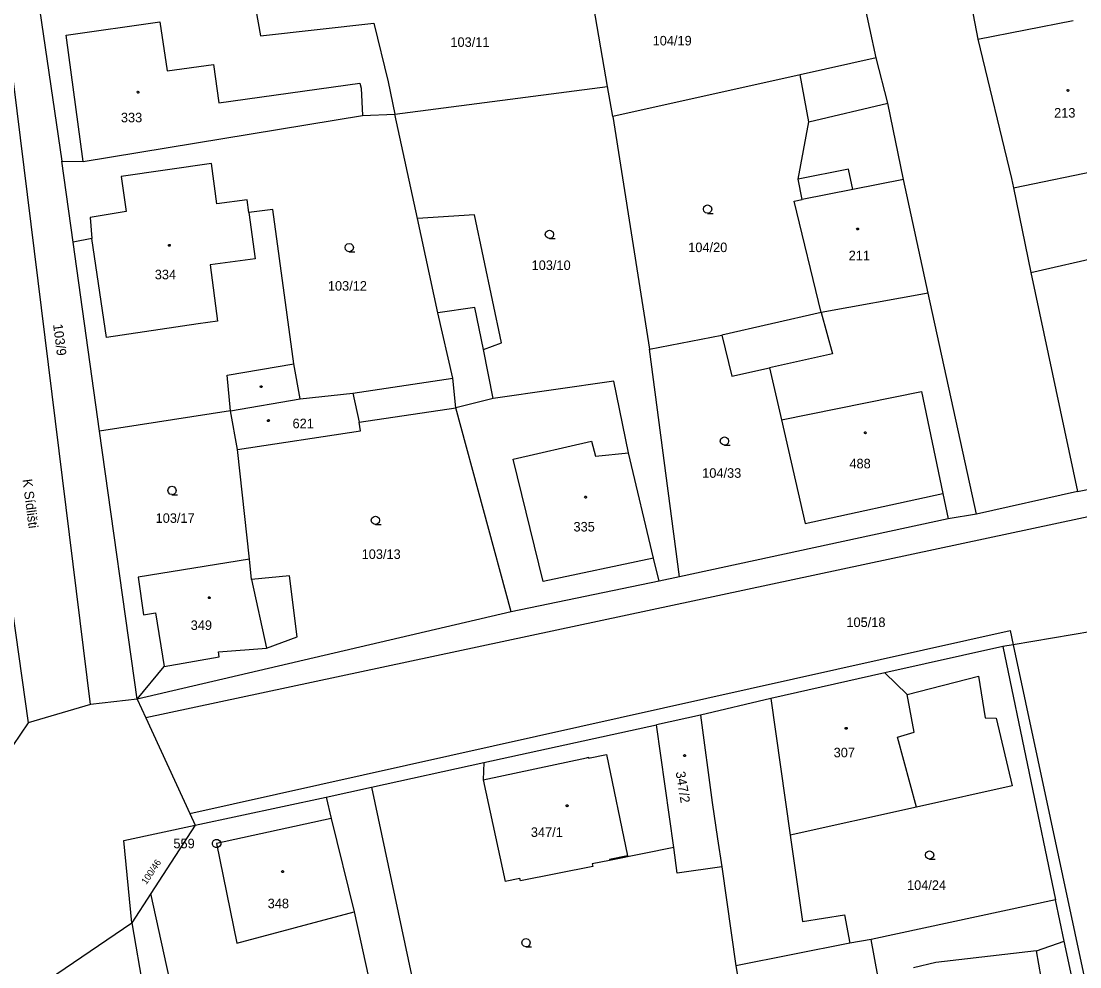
# Model space of a CAD drawing. Extents: x -757994 to -755874, y -1047691 to -1046119.
# Drawn here: x -756803.8 to -756709.6, y -1047154.8 to -1047070.7 of the extents above; entities that cross this region are included whole.
import ezdxf

# ---------------------------------------------------------------- set-up
doc = ezdxf.new("R2010")
doc.units = 0
doc.layers.add('katastrální mapa', color=7, linetype='Continuous')

msp = doc.modelspace()

# ---------------------------------------------------------------- linework, layer by layer
at = {"layer": 'katastrální mapa'}
for p, q in [((-756797.61, -1047131.45), (-756806.3, -1047061.1)), ((-756720.43, -1047063.09), (-756718.67, -1047072.24)), ((-756751.62, -1047076.46), (-756753.8, -1047063.79)), ((-756802.33, -1047068.26), (-756800.17, -1047083.12)), ((-756727.73, -1047073.91), (-756728.84, -1047068.66)), ((-756782.9, -1047069.63), (-756782.48, -1047071.96)), ((-756799.78, -1047071.9), (-756791.44, -1047070.7)), ((-756791.44, -1047070.7), (-756790.78, -1047075.08)), ((-756782.48, -1047071.96), (-756772.4, -1047070.84)), ((-756772.4, -1047070.84), (-756771.14, -1047076.04)), ((-756718.67, -1047072.24), (-756710.2, -1047070.6)), ((-756798.25, -1047083.13), (-756799.78, -1047071.9)), ((-756718.67, -1047072.24), (-756715.68, -1047084.65)), ((-756790.78, -1047075.08), (-756786.68, -1047074.51)), ((-756786.68, -1047074.51), (-756786.2, -1047077.93)), ((-756727.73, -1047073.91), (-756734.49, -1047075.42)), ((-756726.68, -1047077.94), (-756727.73, -1047073.91)), ((-756734.49, -1047075.42), (-756751.14, -1047079.14)), ((-756733.7, -1047079.62), (-756734.49, -1047075.42)), ((-756786.2, -1047077.93), (-756773.64, -1047076.18)), ((-756773.64, -1047076.18), (-756773.52, -1047076.61)), ((-756771.14, -1047076.04), (-756770.54, -1047078.93)), ((-756770.54, -1047078.93), (-756751.62, -1047076.46)), ((-756751.14, -1047079.14), (-756751.62, -1047076.46)), ((-756773.52, -1047076.61), (-756773.43, -1047079.05)), ((-756733.7, -1047079.62), (-756726.68, -1047077.94)), ((-756725.3, -1047084.75), (-756726.68, -1047077.94)), ((-756798.25, -1047083.13), (-756773.43, -1047079.05)), ((-756773.43, -1047079.05), (-756770.54, -1047078.93)), ((-756768.53, -1047088.21), (-756770.54, -1047078.93)), ((-756751.14, -1047079.14), (-756747.9, -1047099.85)), ((-756734.67, -1047084.72), (-756733.7, -1047079.62)), ((-756799.16, -1047090.3), (-756800.17, -1047083.12)), ((-756800.17, -1047083.12), (-756798.25, -1047083.13)), ((-756715.51, -1047085.47), (-756703.12, -1047082.93)), ((-756786.86, -1047083.32), (-756794.88, -1047084.47)), ((-756786.37, -1047086.91), (-756786.86, -1047083.32)), ((-756730.17, -1047083.83), (-756734.67, -1047084.72)), ((-756729.81, -1047085.64), (-756730.17, -1047083.83)), ((-756794.88, -1047084.47), (-756794.45, -1047087.6)), ((-756734.31, -1047086.53), (-756734.67, -1047084.72)), ((-756725.3, -1047084.75), (-756729.81, -1047085.64)), ((-756723.09, -1047094.85), (-756725.3, -1047084.75)), ((-756715.68, -1047084.65), (-756715.51, -1047085.47)), ((-756729.81, -1047085.64), (-756734.31, -1047086.53)), ((-756715.51, -1047085.47), (-756713.97, -1047093.01)), ((-756783.68, -1047086.54), (-756786.37, -1047086.91)), ((-756783.52, -1047087.68), (-756783.68, -1047086.54)), ((-756735.01, -1047086.67), (-756734.31, -1047086.53)), ((-756732.6, -1047096.58), (-756735.01, -1047086.67)), ((-756794.45, -1047087.6), (-756797.65, -1047088.11)), ((-756781.38, -1047087.4), (-756783.52, -1047087.68)), ((-756783.52, -1047087.68), (-756782.96, -1047091.8)), ((-756779.52, -1047101.14), (-756781.38, -1047087.4)), ((-756797.65, -1047088.11), (-756797.48, -1047090)), ((-756763.46, -1047087.89), (-756768.53, -1047088.21)), ((-756766.71, -1047096.61), (-756768.53, -1047088.21)), ((-756761.05, -1047099.28), (-756763.46, -1047087.89)), ((-756713.97, -1047093.01), (-756693.46, -1047088.33)), ((-756797.48, -1047090), (-756799.16, -1047090.3)), ((-756796.81, -1047107.13), (-756799.16, -1047090.3)), ((-756796.2, -1047098.8), (-756797.48, -1047090)), ((-756782.96, -1047091.8), (-756786.98, -1047092.34)), ((-756786.98, -1047092.34), (-756786.3, -1047097.34)), ((-756713.97, -1047093.01), (-756709.82, -1047112.49)), ((-756723.09, -1047094.85), (-756732.6, -1047096.58)), ((-756718.79, -1047114.52), (-756723.09, -1047094.85)), ((-756763.41, -1047096.14), (-756766.71, -1047096.61)), ((-756762.66, -1047099.87), (-756763.41, -1047096.14)), ((-756765.38, -1047102.41), (-756766.71, -1047096.61)), ((-756732.6, -1047096.58), (-756741.46, -1047098.58)), ((-756732.6, -1047096.58), (-756731.62, -1047100.25)), ((-756788.03, -1047097.58), (-756796.2, -1047098.8)), ((-756786.3, -1047097.34), (-756788.03, -1047097.58)), ((-756747.9, -1047099.85), (-756741.46, -1047098.58)), ((-756741.46, -1047098.58), (-756740.56, -1047102.25)), ((-756762.66, -1047099.87), (-756761.05, -1047099.28)), ((-756761.79, -1047104.23), (-756762.66, -1047099.87)), ((-756745.21, -1047120.09), (-756747.9, -1047099.85)), ((-756731.62, -1047100.25), (-756737.2, -1047101.5)), ((-756785.46, -1047102.16), (-756779.52, -1047101.14)), ((-756778.96, -1047104.24), (-756779.52, -1047101.14)), ((-756740.56, -1047102.25), (-756737.2, -1047101.5)), ((-756737.2, -1047101.5), (-756736.14, -1047106.13)), ((-756785.16, -1047105.31), (-756785.46, -1047102.16)), ((-756774.27, -1047103.76), (-756765.38, -1047102.41)), ((-756765.1, -1047105.06), (-756765.38, -1047102.41)), ((-756751.06, -1047102.68), (-756761.79, -1047104.23)), ((-756749.75, -1047109.07), (-756751.06, -1047102.68)), ((-756778.96, -1047104.24), (-756774.27, -1047103.76)), ((-756774.27, -1047103.76), (-756773.7, -1047106.34)), ((-756736.14, -1047106.13), (-756723.7, -1047103.59)), ((-756723.7, -1047103.59), (-756721.79, -1047112.68)), ((-756785.16, -1047105.31), (-756778.96, -1047104.24)), ((-756761.79, -1047104.23), (-756765.1, -1047105.06)), ((-756785.16, -1047105.31), (-756796.81, -1047107.13)), ((-756665.81, -1047105.58), (-756792.7, -1047132.63)), ((-756784.53, -1047108.76), (-756785.16, -1047105.31)), ((-756773.7, -1047106.34), (-756765.1, -1047105.06)), ((-756760.19, -1047123.2), (-756765.1, -1047105.06)), ((-756773.6, -1047107.1), (-756773.7, -1047106.34)), ((-756736.14, -1047106.13), (-756734.03, -1047115.35)), ((-756793.47, -1047130.97), (-756796.81, -1047107.13)), ((-756784.53, -1047108.76), (-756773.6, -1047107.1)), ((-756760.02, -1047109.63), (-756753.05, -1047108.02)), ((-756753.05, -1047108.02), (-756752.68, -1047109.35)), ((-756709.82, -1047112.49), (-756689.77, -1047108.45)), ((-756783.48, -1047118.51), (-756784.53, -1047108.76)), ((-756752.68, -1047109.35), (-756749.75, -1047109.07)), ((-756747.53, -1047118.42), (-756749.75, -1047109.07)), ((-756757.35, -1047120.51), (-756760.02, -1047109.63)), ((-756734.03, -1047115.35), (-756721.79, -1047112.68)), ((-756721.79, -1047112.68), (-756721.32, -1047114.93)), ((-756709.82, -1047112.49), (-756718.79, -1047114.52)), ((-756805.73, -1047114.96), (-756803.17, -1047133.07)), ((-756721.32, -1047114.93), (-756745.21, -1047120.09)), ((-756718.79, -1047114.52), (-756721.32, -1047114.93)), ((-756783.48, -1047118.51), (-756793.38, -1047120.12)), ((-756783.29, -1047120.32), (-756783.48, -1047118.51)), ((-756747.53, -1047118.42), (-756757.35, -1047120.51)), ((-756747.04, -1047120.47), (-756747.53, -1047118.42)), ((-756793.38, -1047120.12), (-756792.9, -1047123.46)), ((-756779.92, -1047120.01), (-756783.29, -1047120.32)), ((-756783.29, -1047120.32), (-756781.97, -1047126.44)), ((-756779.22, -1047125.43), (-756779.92, -1047120.01)), ((-756747.04, -1047120.47), (-756760.19, -1047123.2)), ((-756745.21, -1047120.09), (-756747.04, -1047120.47)), ((-756760.19, -1047123.2), (-756793.47, -1047130.97)), ((-756792.9, -1047123.46), (-756791.82, -1047123.29)), ((-756791.82, -1047123.29), (-756791.07, -1047128.07)), ((-756788.77, -1047141.15), (-756715.8, -1047124.88)), ((-756781.97, -1047126.44), (-756779.22, -1047125.43)), ((-756715.8, -1047124.88), (-756715.54, -1047126.13)), ((-756708.55, -1047124.95), (-756715.54, -1047126.13)), ((-756786.23, -1047126.76), (-756781.97, -1047126.44)), ((-756716.44, -1047126.28), (-756726.95, -1047128.64)), ((-756715.54, -1047126.13), (-756716.44, -1047126.28)), ((-756716.44, -1047126.28), (-756711.77, -1047148.82)), ((-756715.54, -1047126.13), (-756686.13, -1047263.87)), ((-756791.07, -1047128.07), (-756786.16, -1047127.21)), ((-756786.16, -1047127.21), (-756786.23, -1047126.76)), ((-756793.47, -1047130.97), (-756791.07, -1047128.07)), ((-756726.95, -1047128.64), (-756737.1, -1047130.92)), ((-756726.95, -1047128.64), (-756724.96, -1047130.57)), ((-756724.96, -1047130.57), (-756718.63, -1047128.94)), ((-756718.63, -1047128.94), (-756718.02, -1047132.64)), ((-756793.47, -1047130.97), (-756797.61, -1047131.45)), ((-756793.47, -1047130.97), (-756792.7, -1047132.63)), ((-756737.1, -1047130.92), (-756743.35, -1047132.39)), ((-756737.1, -1047130.92), (-756735.37, -1047143.09)), ((-756724.34, -1047133.91), (-756724.96, -1047130.57)), ((-756797.61, -1047131.45), (-756803.17, -1047133.07)), ((-756803.17, -1047133.07), (-756809.22, -1047142.06)), ((-756792.7, -1047132.63), (-756788.77, -1047141.15)), ((-756743.35, -1047132.39), (-756747.26, -1047133.25)), ((-756743.35, -1047132.39), (-756742.32, -1047140.17)), ((-756718.02, -1047132.64), (-756717.06, -1047132.67)), ((-756717.06, -1047132.67), (-756715.62, -1047138.7)), ((-756762.61, -1047136.62), (-756747.26, -1047133.25)), ((-756745.73, -1047144.19), (-756747.26, -1047133.25)), ((-756725.83, -1047134.35), (-756724.34, -1047133.91)), ((-756724.12, -1047140.59), (-756725.83, -1047134.35)), ((-756753.3, -1047136.24), (-756751.7, -1047135.89)), ((-756751.7, -1047135.89), (-756749.85, -1047144.91)), ((-756772.63, -1047138.82), (-756762.61, -1047136.62)), ((-756762.68, -1047138.17), (-756753.5, -1047136.19)), ((-756762.61, -1047136.62), (-756762.68, -1047138.17)), ((-756753.5, -1047136.19), (-756753.32, -1047136.15)), ((-756753.32, -1047136.15), (-756753.3, -1047136.24)), ((-756762.68, -1047138.17), (-756760.73, -1047147.19)), ((-756715.62, -1047138.7), (-756724.12, -1047140.59)), ((-756776.66, -1047139.69), (-756772.63, -1047138.82)), ((-756772.63, -1047138.82), (-756767.41, -1047163.3)), ((-756788.29, -1047142.19), (-756776.66, -1047139.69)), ((-756776.66, -1047139.69), (-756776.19, -1047141.6)), ((-756742.32, -1047140.17), (-756741.85, -1047143.41)), ((-756724.12, -1047140.59), (-756735.37, -1047143.09)), ((-756788.77, -1047141.15), (-756788.29, -1047142.19)), ((-756794.64, -1047143.55), (-756788.29, -1047142.19)), ((-756788.29, -1047142.19), (-756792.24, -1047148.27)), ((-756776.19, -1047141.6), (-756786.39, -1047143.82)), ((-756776.19, -1047141.6), (-756774.17, -1047149.9)), ((-756741.85, -1047143.41), (-756741.44, -1047145.9)), ((-756735.37, -1047143.09), (-756734.28, -1047150.76)), ((-756793.93, -1047150.88), (-756794.64, -1047143.55)), ((-756786.415, -1047143.82), (-756786.365, -1047143.82)), ((-756786.39, -1047143.82), (-756784.58, -1047152.7)), ((-756745.73, -1047144.19), (-756751.43, -1047145.33)), ((-756745.41, -1047146.46), (-756745.73, -1047144.19)), ((-756751.43, -1047145.33), (-756752.98, -1047145.64)), ((-756749.85, -1047144.91), (-756751.45, -1047145.23)), ((-756751.45, -1047145.23), (-756751.43, -1047145.33)), ((-756752.94, -1047145.86), (-756759.37, -1047147.14)), ((-756752.98, -1047145.64), (-756752.94, -1047145.86)), ((-756741.44, -1047145.9), (-756745.41, -1047146.46)), ((-756741.44, -1047145.9), (-756740.2, -1047154.72)), ((-756759.42, -1047146.93), (-756760.73, -1047147.19)), ((-756759.37, -1047147.14), (-756759.42, -1047146.93)), ((-756792.24, -1047148.27), (-756793.93, -1047150.88)), ((-756787.99, -1047167.7), (-756792.24, -1047148.27)), ((-756711.77, -1047148.82), (-756728.16, -1047152.37)), ((-756710.99, -1047152.52), (-756711.77, -1047148.82)), ((-756784.58, -1047152.7), (-756774.17, -1047149.9)), ((-756774.17, -1047149.9), (-756771.02, -1047164.16)), ((-756805.16, -1047158.5), (-756793.93, -1047150.88)), ((-756793.93, -1047150.88), (-756790.93, -1047168.29)), ((-756734.28, -1047150.76), (-756730.55, -1047150.18)), ((-756730.55, -1047150.18), (-756730.05, -1047152.68)), ((-756730.05, -1047152.68), (-756740.2, -1047154.72)), ((-756728.16, -1047152.37), (-756730.05, -1047152.68)), ((-756727.57, -1047155.59), (-756728.16, -1047152.37)), ((-756713.46, -1047153.37), (-756710.99, -1047152.52)), ((-756706.92, -1047171.68), (-756710.99, -1047152.52)), ((-756713.46, -1047153.37), (-756722.42, -1047154.41)), ((-756711.7, -1047163.55), (-756713.46, -1047153.37)), ((-756740.2, -1047154.72), (-756739.68, -1047157.74)), ((-756722.42, -1047154.41), (-756724.39, -1047154.87))]:
    msp.add_line(p, q, dxfattribs=at)
for points in [[(-756793.4, -1047076.885), (-756793.35, -1047076.895), (-756793.325, -1047076.94), (-756793.315, -1047076.97), (-756793.325, -1047077.015), (-756793.365, -1047077.05), (-756793.4, -1047077.055), (-756793.445, -1047077.04), (-756793.475, -1047077.01), (-756793.485, -1047076.97), (-756793.475, -1047076.925), (-756793.435, -1047076.89)], [(-756710.65, -1047076.725), (-756710.6, -1047076.735), (-756710.575, -1047076.78), (-756710.565, -1047076.81), (-756710.575, -1047076.855), (-756710.615, -1047076.89), (-756710.65, -1047076.895), (-756710.695, -1047076.88), (-756710.725, -1047076.85), (-756710.735, -1047076.81), (-756710.725, -1047076.765), (-756710.685, -1047076.73)], [(-756729.38, -1047089.055), (-756729.33, -1047089.065), (-756729.305, -1047089.11), (-756729.295, -1047089.14), (-756729.305, -1047089.185), (-756729.345, -1047089.22), (-756729.38, -1047089.225), (-756729.425, -1047089.21), (-756729.455, -1047089.18), (-756729.465, -1047089.14), (-756729.455, -1047089.095), (-756729.415, -1047089.06)], [(-756790.59, -1047090.515), (-756790.54, -1047090.525), (-756790.515, -1047090.57), (-756790.505, -1047090.6), (-756790.515, -1047090.645), (-756790.555, -1047090.68), (-756790.59, -1047090.685), (-756790.635, -1047090.67), (-756790.665, -1047090.64), (-756790.675, -1047090.6), (-756790.665, -1047090.555), (-756790.625, -1047090.52)], [(-756782.385, -1047103.105), (-756782.34, -1047103.18), (-756782.385, -1047103.255), (-756782.475, -1047103.255), (-756782.52, -1047103.18), (-756782.475, -1047103.105)], [(-756781.78, -1047106.105), (-756781.73, -1047106.115), (-756781.705, -1047106.16), (-756781.695, -1047106.19), (-756781.705, -1047106.235), (-756781.745, -1047106.27), (-756781.78, -1047106.275), (-756781.825, -1047106.26), (-756781.855, -1047106.23), (-756781.865, -1047106.19), (-756781.855, -1047106.145), (-756781.815, -1047106.11)], [(-756728.68, -1047107.185), (-756728.63, -1047107.195), (-756728.605, -1047107.24), (-756728.595, -1047107.27), (-756728.605, -1047107.315), (-756728.645, -1047107.35), (-756728.68, -1047107.355), (-756728.725, -1047107.34), (-756728.755, -1047107.31), (-756728.765, -1047107.27), (-756728.755, -1047107.225), (-756728.715, -1047107.19)], [(-756753.57, -1047112.915), (-756753.52, -1047112.925), (-756753.495, -1047112.97), (-756753.485, -1047113), (-756753.495, -1047113.045), (-756753.535, -1047113.08), (-756753.57, -1047113.085), (-756753.615, -1047113.07), (-756753.645, -1047113.04), (-756753.655, -1047113), (-756753.645, -1047112.955), (-756753.605, -1047112.92)], [(-756787.04, -1047121.865), (-756786.99, -1047121.875), (-756786.965, -1047121.92), (-756786.955, -1047121.95), (-756786.965, -1047121.995), (-756787.005, -1047122.03), (-756787.04, -1047122.035), (-756787.085, -1047122.02), (-756787.115, -1047121.99), (-756787.125, -1047121.95), (-756787.115, -1047121.905), (-756787.075, -1047121.87)], [(-756730.39, -1047133.485), (-756730.34, -1047133.495), (-756730.315, -1047133.54), (-756730.305, -1047133.57), (-756730.315, -1047133.615), (-756730.355, -1047133.65), (-756730.39, -1047133.655), (-756730.435, -1047133.64), (-756730.465, -1047133.61), (-756730.475, -1047133.57), (-756730.465, -1047133.525), (-756730.425, -1047133.49)], [(-756744.77, -1047135.915), (-756744.72, -1047135.925), (-756744.695, -1047135.97), (-756744.685, -1047136), (-756744.695, -1047136.045), (-756744.735, -1047136.08), (-756744.77, -1047136.085), (-756744.815, -1047136.07), (-756744.845, -1047136.04), (-756744.855, -1047136), (-756744.845, -1047135.955), (-756744.805, -1047135.92)], [(-756755.21, -1047140.375), (-756755.16, -1047140.385), (-756755.135, -1047140.43), (-756755.125, -1047140.46), (-756755.135, -1047140.505), (-756755.175, -1047140.54), (-756755.21, -1047140.545), (-756755.255, -1047140.53), (-756755.285, -1047140.5), (-756755.295, -1047140.46), (-756755.285, -1047140.415), (-756755.245, -1047140.38)], [(-756786.295, -1047143.46), (-756786.125, -1047143.555), (-756786.03, -1047143.725), (-756786.03, -1047143.92), (-756786.125, -1047144.09), (-756786.295, -1047144.185), (-756786.49, -1047144.185), (-756786.66, -1047144.09), (-756786.755, -1047143.92), (-756786.755, -1047143.725), (-756786.66, -1047143.555), (-756786.49, -1047143.46)], [(-756780.53, -1047146.235), (-756780.48, -1047146.245), (-756780.455, -1047146.29), (-756780.445, -1047146.32), (-756780.455, -1047146.365), (-756780.495, -1047146.4), (-756780.53, -1047146.405), (-756780.575, -1047146.39), (-756780.605, -1047146.36), (-756780.615, -1047146.32), (-756780.605, -1047146.275), (-756780.565, -1047146.24)]]:
    msp.add_lwpolyline(points, close=True, dxfattribs=at)
for points in [[(-756742.72, -1047087.74), (-756742.91, -1047087.69), (-756743.045, -1047087.555), (-756743.095, -1047087.37), (-756743.045, -1047087.185), (-756742.91, -1047087.05), (-756742.725, -1047087), (-756742.54, -1047087.05), (-756742.405, -1047087.185), (-756742.355, -1047087.375), (-756742.405, -1047087.565), (-756742.54, -1047087.7), (-756742.73, -1047087.75), (-756742.23, -1047087.75)], [(-756756.78, -1047089.99), (-756756.97, -1047089.94), (-756757.105, -1047089.805), (-756757.155, -1047089.62), (-756757.105, -1047089.435), (-756756.97, -1047089.3), (-756756.785, -1047089.25), (-756756.6, -1047089.3), (-756756.465, -1047089.435), (-756756.415, -1047089.625), (-756756.465, -1047089.815), (-756756.6, -1047089.95), (-756756.79, -1047090), (-756756.29, -1047090)], [(-756774.59, -1047091.16), (-756774.78, -1047091.11), (-756774.915, -1047090.975), (-756774.965, -1047090.79), (-756774.915, -1047090.605), (-756774.78, -1047090.47), (-756774.595, -1047090.42), (-756774.41, -1047090.47), (-756774.275, -1047090.605), (-756774.225, -1047090.795), (-756774.275, -1047090.985), (-756774.41, -1047091.12), (-756774.6, -1047091.17), (-756774.1, -1047091.17)], [(-756741.21, -1047108.38), (-756741.4, -1047108.33), (-756741.535, -1047108.195), (-756741.585, -1047108.01), (-756741.535, -1047107.825), (-756741.4, -1047107.69), (-756741.215, -1047107.64), (-756741.03, -1047107.69), (-756740.895, -1047107.825), (-756740.845, -1047108.015), (-756740.895, -1047108.205), (-756741.03, -1047108.34), (-756741.22, -1047108.39), (-756740.72, -1047108.39)], [(-756790.36, -1047112.78), (-756790.55, -1047112.73), (-756790.685, -1047112.595), (-756790.735, -1047112.41), (-756790.685, -1047112.225), (-756790.55, -1047112.09), (-756790.365, -1047112.04), (-756790.18, -1047112.09), (-756790.045, -1047112.225), (-756789.995, -1047112.415), (-756790.045, -1047112.605), (-756790.18, -1047112.74), (-756790.37, -1047112.79), (-756789.87, -1047112.79)], [(-756772.26, -1047115.43), (-756772.45, -1047115.38), (-756772.585, -1047115.245), (-756772.635, -1047115.06), (-756772.585, -1047114.875), (-756772.45, -1047114.74), (-756772.265, -1047114.69), (-756772.08, -1047114.74), (-756771.945, -1047114.875), (-756771.895, -1047115.065), (-756771.945, -1047115.255), (-756772.08, -1047115.39), (-756772.27, -1047115.44), (-756771.77, -1047115.44)], [(-756722.97, -1047145.21), (-756723.16, -1047145.16), (-756723.295, -1047145.025), (-756723.345, -1047144.84), (-756723.295, -1047144.655), (-756723.16, -1047144.52), (-756722.975, -1047144.47), (-756722.79, -1047144.52), (-756722.655, -1047144.655), (-756722.605, -1047144.845), (-756722.655, -1047145.035), (-756722.79, -1047145.17), (-756722.98, -1047145.22), (-756722.48, -1047145.22)], [(-756758.87, -1047153.02), (-756759.06, -1047152.97), (-756759.195, -1047152.835), (-756759.245, -1047152.65), (-756759.195, -1047152.465), (-756759.06, -1047152.33), (-756758.875, -1047152.28), (-756758.69, -1047152.33), (-756758.555, -1047152.465), (-756758.505, -1047152.655), (-756758.555, -1047152.845), (-756758.69, -1047152.98), (-756758.88, -1047153.03), (-756758.38, -1047153.03)]]:
    msp.add_lwpolyline(points, dxfattribs=at)

# ---------------------------------------------------------------- texts
for s, p in [('103/11', (-756765.596, -1047072.94)), ('104/19', (-756747.607, -1047072.81)), ('213', (-756711.893, -1047079.23)), ('333', (-756794.908, -1047079.65)), ('104/20', (-756744.441, -1047091.2)), ('211', (-756730.166, -1047091.92)), ('103/10', (-756758.373, -1047092.79)), ('334', (-756791.894, -1047093.62)), ('103/12', (-756776.497, -1047094.63)), ('621', (-756779.64, -1047106.87)), ('104/33', (-756743.198, -1047111.28)), ('488', (-756730.101, -1047110.44)), ('103/17', (-756791.82, -1047115.29)), ('335', (-756754.648, -1047116.06)), ('103/13', (-756773.494, -1047118.5)), ('105/18', (-756730.37, -1047124.56)), ('349', (-756788.701, -1047124.82)), ('307', (-756731.504, -1047136.15)), ('347/1', (-756758.441, -1047143.24)), ('559', (-756790.237, -1047144.245)), ('104/24', (-756724.977, -1047147.95)), ('348', (-756781.851, -1047149.58))]:
    msp.add_text(s, height=0.85, dxfattribs=at).set_placement(p)
for s, height, rotation, p in [('103/9', 0.85, 277.31157, (-756800.944, -1047097.644)), ('K Sídlišti', 0.85, 277.19698, (-756803.658, -1047111.439)), ('347/2', 0.85, 279.31693, (-756745.561, -1047137.467)), ('100/46', 0.595, 56.20716, (-756792.644, -1047147.516))]:
    msp.add_text(s, height=height, rotation=rotation, dxfattribs=at).set_placement(p)

doc.saveas('drawing.dxf')
